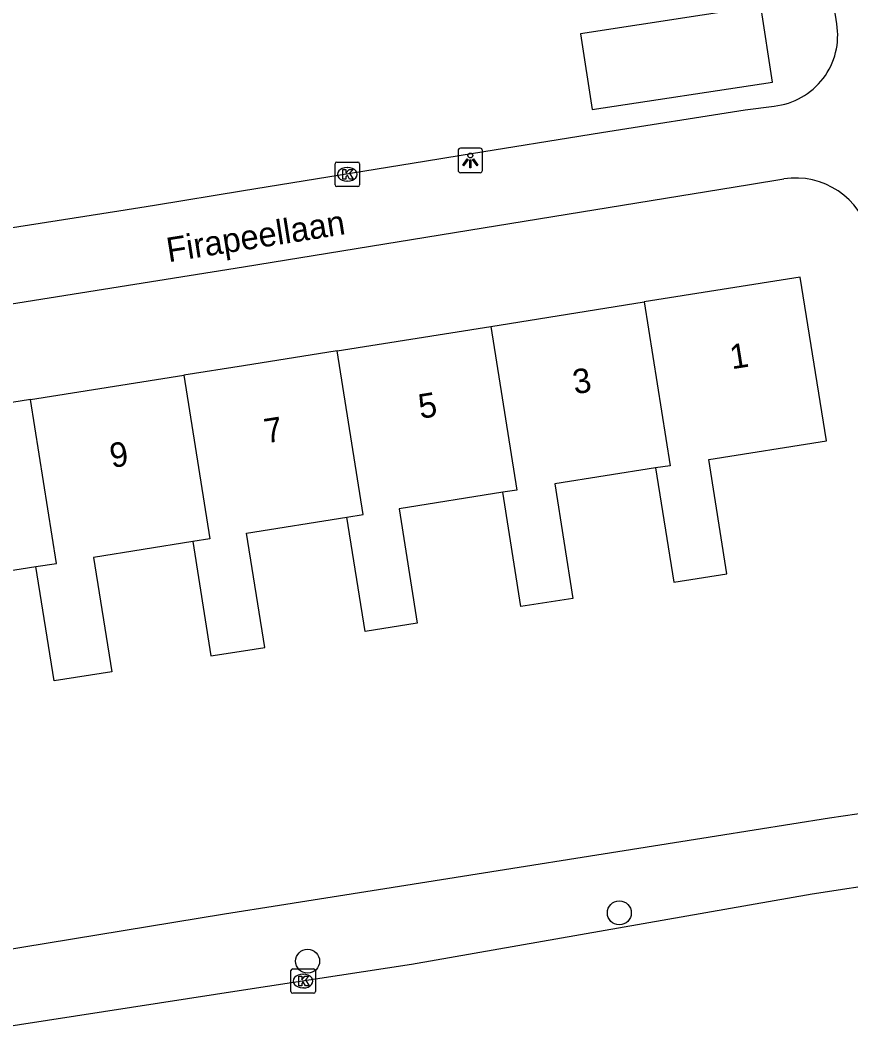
# Model space of a CAD drawing. Extents: x 160077 to 160945, y 386481 to 387498.
# Drawn here: x 160490.87 to 160524.81, y 387334.18 to 387375.45 of the extents above; entities that cross this region are included whole.
import ezdxf

# ---------------------------------------------------------------- set-up
doc = ezdxf.new("R2010")
doc.units = 0
for name, color, linetype in [('IMGEO_Boom', 7, 'Continuous'), ('IMGEO_Kolk', 7, 'Continuous'), ('IMGEO_Lichtpunt', 7, 'Continuous'), ('IMGEO_Openbare_ruimte_label', 7, 'Continuous'), ('IMGEO_Pand', 7, 'Continuous'), ('IMGEO_Pand_nummerreeks', 7, 'Continuous'), ('IMGEO_Rijbaan_lokaal_open', 7, 'Continuous'), ('IMGEO_Voetpad_open', 7, 'Continuous')]:
    doc.layers.add(name, color=color, linetype=linetype)

msp = doc.modelspace()

# ---------------------------------------------------------------- linework, layer by layer
at = {"layer": 'IMGEO_Boom'}
for centre in [(160515.351, 387338.99), (160502.615, 387337.017)]:
    msp.add_circle(centre, 0.489, dxfattribs=at)
at = {"layer": 'IMGEO_Kolk'}
for p, q in [((160503.737, 387368.729), (160503.737, 387369.581)), ((160503.812, 387369.655), (160504.664, 387369.655)), ((160504.738, 387369.581), (160504.738, 387368.729)), ((160504.225, 387369.435), (160504.25, 387369.435)), ((160504.664, 387368.655), (160503.812, 387368.655)), ((160504.248, 387368.875), (160504.223, 387368.875)), ((160501.931, 387335.781), (160501.931, 387336.633)), ((160502.006, 387336.707), (160502.858, 387336.707)), ((160502.419, 387336.487), (160502.444, 387336.487)), ((160502.932, 387336.633), (160502.932, 387335.781)), ((160502.858, 387335.707), (160502.006, 387335.707)), ((160502.442, 387335.927), (160502.417, 387335.927))]:
    msp.add_line(p, q, dxfattribs=at)
for points in [[(160503.737, 387368.729), (160503.737, 387369.581)], [(160503.812, 387369.655), (160504.664, 387369.655)], [(160504.738, 387369.581), (160504.738, 387368.729)], [(160504.058, 387369.355), (160504.181, 387369.355), (160504.181, 387369.204), (160504.311, 387369.355), (160504.475, 387369.355), (160504.329, 387369.204), (160504.482, 387368.955), (160504.33, 387368.955), (160504.245, 387369.119), (160504.181, 387369.052), (160504.181, 387368.955), (160504.058, 387368.955), (160504.058, 387369.355)], [(160504.664, 387368.655), (160503.812, 387368.655)], [(160501.931, 387335.781), (160501.931, 387336.633)], [(160502.006, 387336.707), (160502.858, 387336.707)], [(160502.932, 387336.633), (160502.932, 387335.781)], [(160502.252, 387336.407), (160502.375, 387336.407), (160502.375, 387336.256), (160502.505, 387336.407), (160502.669, 387336.407), (160502.523, 387336.256), (160502.676, 387336.007), (160502.524, 387336.007), (160502.439, 387336.171), (160502.375, 387336.104), (160502.375, 387336.007), (160502.252, 387336.007), (160502.252, 387336.407)], [(160502.858, 387335.707), (160502.006, 387335.707)]]:
    msp.add_lwpolyline(points, dxfattribs=at)
for centre, start, end in [((160503.814, 387369.579), 91.552, 178.448), ((160503.814, 387369.579), 91.552, 178.448), ((160504.662, 387369.579), 1.552, 88.448), ((160504.662, 387369.579), 1.552, 88.448), ((160503.814, 387368.731), 181.552, 268.448), ((160503.814, 387368.731), 181.552, 268.448), ((160504.662, 387368.731), 271.552, 358.448), ((160504.662, 387368.731), 271.552, 358.448), ((160502.008, 387336.631), 91.552, 178.448), ((160502.008, 387336.631), 91.552, 178.448), ((160502.856, 387336.631), 1.552, 88.448), ((160502.856, 387336.631), 1.552, 88.448), ((160502.008, 387335.783), 181.552, 268.448), ((160502.008, 387335.783), 181.552, 268.448), ((160502.856, 387335.783), 271.552, 358.448), ((160502.856, 387335.783), 271.552, 358.448)]:
    msp.add_arc(centre, 0.0765, start, end, dxfattribs=at)
for centre, major_axis, ratio, start_param, end_param in [((160504.224, 387369.155), (-0.387, 0.002), 0.722429, 4.712389, 7.853982), ((160504.249, 387369.155), (-0.39, 0.002), 0.717154, 1.570796, 4.712389), ((160502.418, 387336.207), (-0.387, 0.002), 0.722429, 4.712389, 7.853982), ((160502.443, 387336.207), (-0.39, 0.002), 0.717154, 1.570796, 4.712389)]:
    msp.add_ellipse(centre, major_axis=major_axis, ratio=ratio, start_param=start_param, end_param=end_param, dxfattribs=at)
at = {"layer": 'IMGEO_Lichtpunt'}
for p, q in [((160508.764, 387370.123), (160508.764, 387369.316)), ((160508.764, 387370.123), (160508.764, 387369.316)), ((160509.666, 387370.218), (160508.858, 387370.218)), ((160509.666, 387370.218), (160508.858, 387370.218)), ((160509.76, 387369.316), (160509.76, 387370.123)), ((160509.76, 387369.316), (160509.76, 387370.123)), ((160508.858, 387369.222), (160509.666, 387369.222)), ((160508.858, 387369.222), (160509.666, 387369.222))]:
    msp.add_line(p, q, dxfattribs=at)
for points in [[(160509.138, 387369.787), (160509.177, 387369.759), (160508.989, 387369.497), (160508.951, 387369.524), (160509.138, 387369.787)], [(160509.24, 387369.739), (160509.287, 387369.739), (160509.287, 387369.417), (160509.24, 387369.417), (160509.24, 387369.739)], [(160509.35, 387369.759), (160509.388, 387369.786), (160509.575, 387369.524), (160509.536, 387369.496), (160509.35, 387369.759)]]:
    msp.add_lwpolyline(points, dxfattribs=at)
msp.add_circle((160509.263, 387369.921), 0.0994, dxfattribs=at)
for centre, start, end in [((160508.858, 387370.123), 90, 180), ((160508.858, 387370.123), 90, 180), ((160509.666, 387370.123), 0, 90), ((160509.666, 387370.123), 0, 90), ((160508.858, 387369.316), 180, 270), ((160508.858, 387369.316), 180, 270), ((160509.666, 387369.316), 270, 0), ((160509.666, 387369.316), 270, 360)]:
    msp.add_arc(centre, 0.0946, start, end, dxfattribs=at)
at = {"layer": 'IMGEO_Pand'}
for points in [[(160514.236, 387371.797), (160521.606, 387372.915), (160521.136, 387376.016), (160513.766, 387374.898), (160514.236, 387371.797)], [(160516.834, 387357.162), (160517.576, 387352.493), (160519.746, 387352.838), (160519.003, 387357.507), (160523.81, 387358.271), (160522.747, 387364.956), (160516.368, 387363.942)], [(160510.098, 387362.945), (160516.368, 387363.942)], [(160516.368, 387363.942), (160517.431, 387357.255), (160516.834, 387357.162)], [(160503.828, 387361.948), (160510.098, 387362.945)], [(160510.098, 387362.945), (160511.16, 387356.261), (160510.59, 387356.17)], [(160503.828, 387361.948), (160500, 387361.339), (160497.557, 387360.95)], [(160504.219, 387355.157), (160504.891, 387355.261), (160503.828, 387361.948)], [(160491.287, 387359.953), (160497.557, 387360.95)], [(160497.557, 387360.95), (160498.62, 387354.265), (160497.925, 387354.156)], [(160491.287, 387359.953), (160484.911, 387358.939), (160485.974, 387352.255), (160485.152, 387352.124), (160485.895, 387347.454), (160488.12, 387347.808), (160487.377, 387352.478), (160491.513, 387353.136)], [(160491.513, 387353.136), (160492.35, 387353.267), (160491.287, 387359.953)], [(160516.834, 387357.162), (160512.713, 387356.507), (160513.456, 387351.837), (160511.333, 387351.5), (160510.59, 387356.17)], [(160510.59, 387356.17), (160506.354, 387355.496), (160507.096, 387350.827), (160504.961, 387350.487), (160504.219, 387355.157)], [(160497.925, 387354.156), (160498.667, 387349.486), (160500, 387349.698), (160500.862, 387349.835), (160500.12, 387354.505), (160504.219, 387355.157)], [(160497.925, 387354.156), (160493.867, 387353.511), (160494.61, 387348.841), (160492.256, 387348.467), (160491.513, 387353.136)]]:
    msp.add_lwpolyline(points, dxfattribs=at)
at = {"layer": 'IMGEO_Rijbaan_lokaal_open'}
msp.add_lwpolyline([(160528.643, 387340.566), (160526.431, 387340.245), (160523.231, 387339.751), (160506.86, 387336.889), (160500, 387335.831), (160480.714, 387332.858), (160477.592, 387332.362)], dxfattribs=at)
at = {"layer": 'IMGEO_Voetpad_open'}
for points in [[(160524.236, 387375.303), (160521.083, 387395.524)], [(160484.327, 387365.994), (160489.406, 387366.799), (160494.896, 387367.669), (160496.357, 387367.901), (160500, 387368.49), (160507.39, 387369.685), (160508.893, 387369.93), (160514.628, 387370.867), (160520.489, 387371.785), (160521.678, 387371.943)], [(160484.096, 387362.839), (160500, 387365.375), (160520.672, 387368.738), (160522.075, 387368.967)], [(160488.852, 387337.254), (160499.213, 387338.948), (160500, 387339.075), (160500.683, 387339.185), (160505.767, 387339.991), (160519.324, 387342.142), (160523.935, 387342.867), (160526.171, 387343.197)]]:
    msp.add_lwpolyline(points, dxfattribs=at)
for centre, radius, start, end in [((160521.374, 387374.828), 2.901, 276.0159, 9.4194), ((160522.55, 387365.866), 3.138, 13.7995, 98.7078)]:
    msp.add_arc(centre, radius, start, end, dxfattribs=at)

# ---------------------------------------------------------------- texts
at = {"layer": 'IMGEO_Openbare_ruimte_label'}
msp.add_text('Firapeellaan', height=1, rotation=9.0292, dxfattribs=at).set_placement((160496.932, 387365.561))
at = {"layer": 'IMGEO_Pand_nummerreeks'}
for s, p in [('1', (160519.949, 387361.19)), ('3', (160513.53, 387360.169)), ('5', (160507.224, 387359.166)), ('7', (160500.918, 387358.163)), ('9', (160494.612, 387357.16))]:
    msp.add_text(s, height=1, rotation=9.036, dxfattribs=at).set_placement(p)

doc.saveas('drawing.dxf')
